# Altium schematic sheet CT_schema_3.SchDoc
size 313 x 185 mm
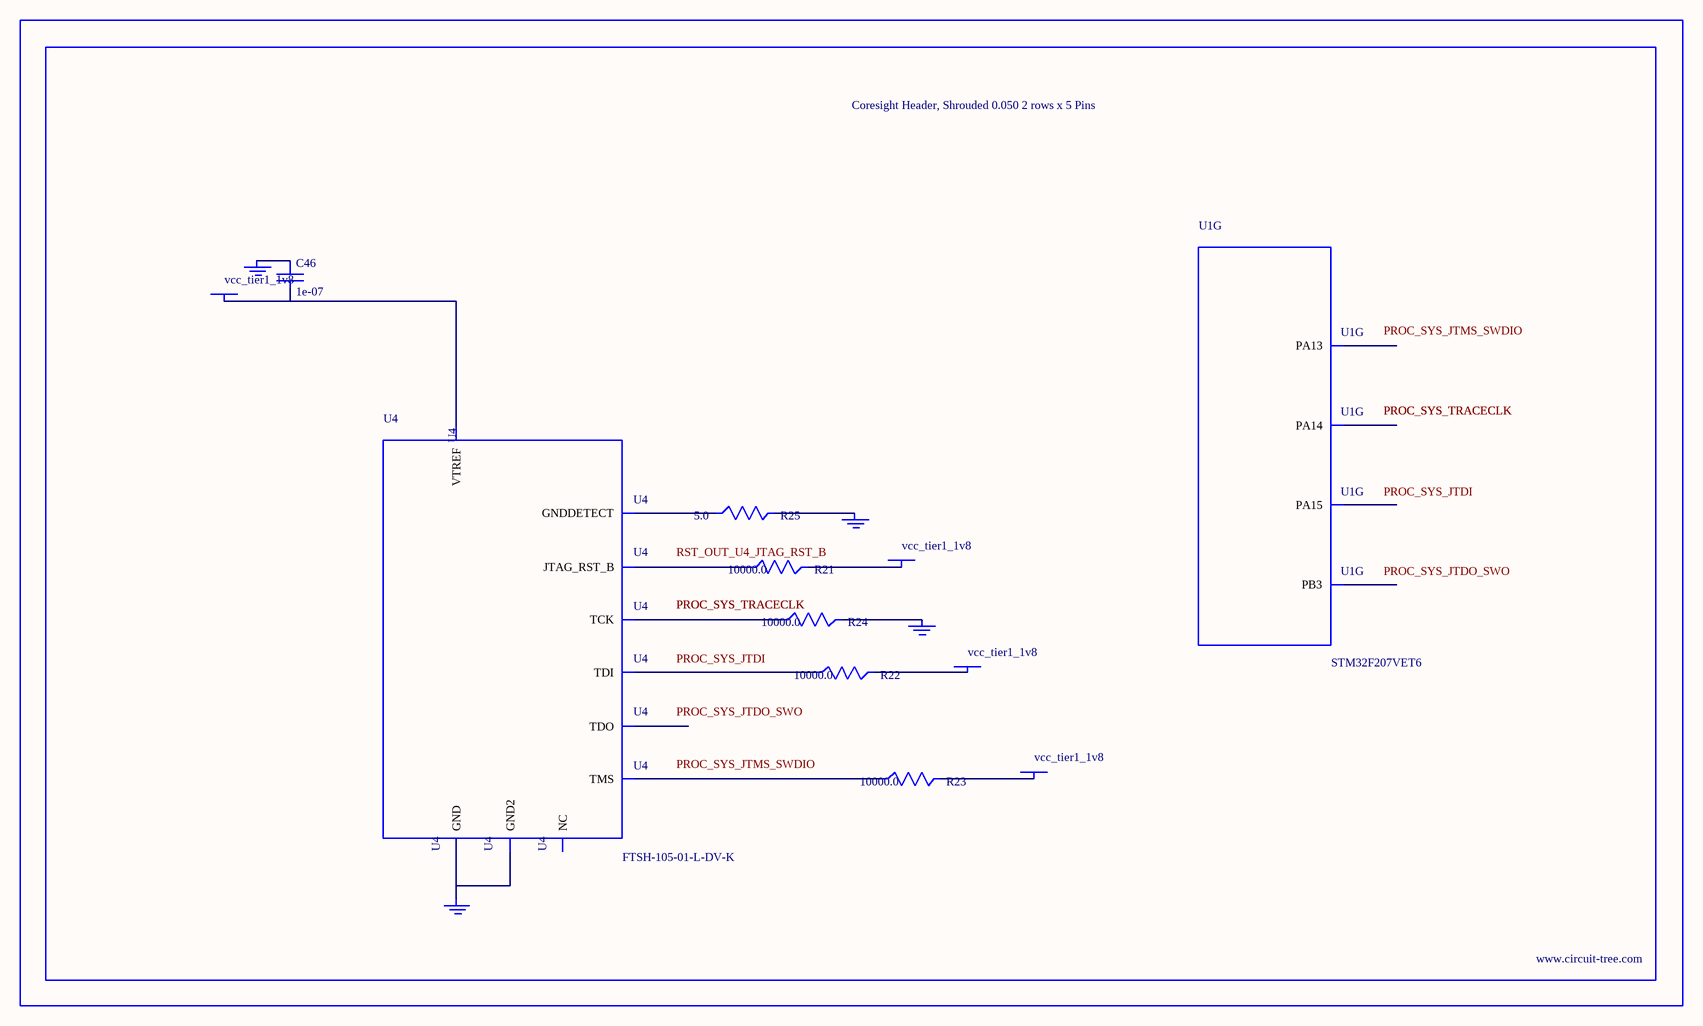
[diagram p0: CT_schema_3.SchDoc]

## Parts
BORDER2  (no value)
C46  1e-07  [C0402]
GND_INSTANCE_2_0  (no value)
GND_INSTANCE_2_1  (no value)
GND_INSTANCE_2_2  (no value)
GND_INSTANCE_2_3  (no value)
POWER_INSTANCE_2_0  vcc_tier1_1v8
POWER_INSTANCE_2_1  vcc_tier1_1v8
POWER_INSTANCE_2_2  vcc_tier1_1v8
POWER_INSTANCE_2_3  vcc_tier1_1v8
R21  10000.0  [R0603]
R22  10000.0  [R0603]
R23  10000.0  [R0603]
R24  10000.0  [R0603]
R25  5.0  [R0603]
U1  STM32F207VET6  [LQFP100]  (part G of 9)
U4  FTSH-105-01-L-DV-K  [SAMTEC_FTSH-105-01-L-DV-K]

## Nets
NetC46_1: C46.1 GND_INSTANCE_2_0.0(GND)
NetC46_2: C46.2 POWER_INSTANCE_2_0.0(PWR) U4.1(VTREF)
NetGND_INSTANCE_2_1_0: GND_INSTANCE_2_1.0(GND) R24.2
NetGND_INSTANCE_2_2_0: GND_INSTANCE_2_2.0(GND) R25.2
NetGND_INSTANCE_2_3_0: GND_INSTANCE_2_3.0(GND) U4.3(GND) U4.5(GND2)
NetPOWER_INSTANCE_2_1_0: POWER_INSTANCE_2_1.0(PWR) R23.2
NetPOWER_INSTANCE_2_2_0: POWER_INSTANCE_2_2.0(PWR) R22.2
NetPOWER_INSTANCE_2_3_0: POWER_INSTANCE_2_3.0(PWR) R21.2
NetR21_1: R21.1 U4.10(JTAG_RST_B)
NetR22_1: R22.1 U4.8(TDI)
NetR23_1: R23.1 U4.2(TMS)
NetR24_1: R24.1 U4.4(TCK)
NetR25_1: R25.1 U4.9(GNDDETECT)

Not connected (* = marked no-connect by the designer): U1 72(PA13) 76(PA14) 77(PA15) 89(PB3); U4 6(TDO) 7(NC)

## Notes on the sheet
- Labels drawn without touching a wire or pin: PROC_SYS_JTDI, PROC_SYS_JTDO_SWO, PROC_SYS_JTMS_SWDIO, RST_OUT_U4_JTAG_RST_B

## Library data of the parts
BORDER2 = BORDER_PAGE2
C46 = C0402C104K3RACTU
GND_INSTANCE_2_0-GND_INSTANCE_2_3 = GND
POWER_INSTANCE_2_0-POWER_INSTANCE_2_3 = PWR
R21-R24 = RC0603JR-0710KL
R25 = ERJ-3GEYJ5R1V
